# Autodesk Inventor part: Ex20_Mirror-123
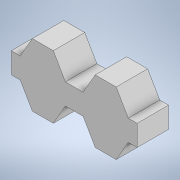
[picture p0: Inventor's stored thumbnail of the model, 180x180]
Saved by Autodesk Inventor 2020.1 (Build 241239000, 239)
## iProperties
Created: 2019-11
Part Number: Ex20_Mirror-123
Material: Generic
Document SubType Name: Modeling
Designer: Synergysoft Dell02
Density: 1 g/cm^3
Appearance: Default
Author: Synergysoft Dell02
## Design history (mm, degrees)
sketch "Sketch1"
  geometry: L1 (0, 0)-(-30, 0); L2 (-30, 0)-(-30, 10); L3 (-30, 10)-(-21.547, 10); L4 (-21.547, 10)-(-10, 30); L5 (-10, 30)-(0, 30); L6 (0, 30)-(0, 0)
  constraints: 12 end point, 3 perpendicular, 1 horizontal, 1 parallel
  dimensions: "d0" = 30 distance of L1.start L1.end; "d1" = 10 distance of L1.end L2.end; "d2" = 30 distance of L5.end L1.start; "d3" = 10 distance of L4.end L5.end; "d4" = 30 deg angle of L6 L4
extrude "Extrusion1" new body sketch "Sketch1" distance "d5" = 15; taper "d6" = 0 deg
mirror "Mirror1"
mirror "Mirror2"
mirror "Mirror3"
mirror "Mirror4"
body "Solid1"
